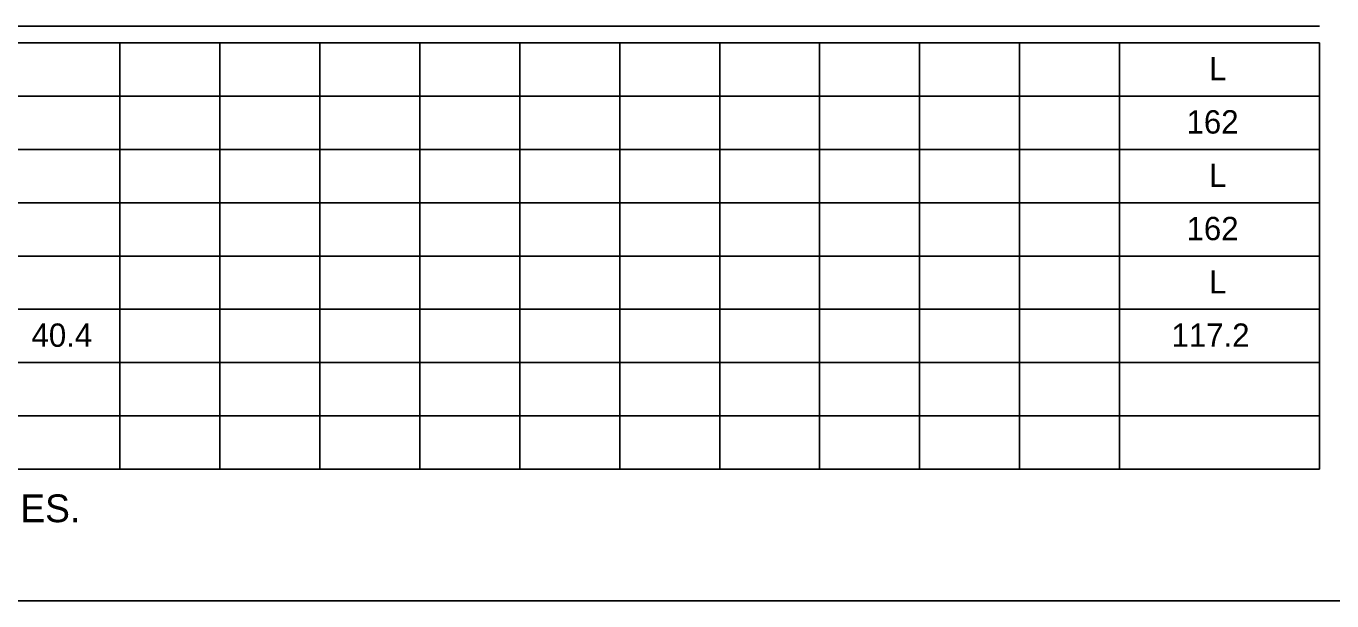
# Model space of a CAD drawing. Extents: x 10268312 to 10268472, y 2142583 to 2142688.
# Drawn here: x 10268355.16 to 10268394.36, y 2142640.28 to 2142657.53 of the extents above; entities that cross this region are included whole.
import ezdxf

# ---------------------------------------------------------------- set-up
doc = ezdxf.new("R2010")
doc.units = 0
for name, color, linetype in [('SheetBorder_dp', 7, 'Continuous'), ('SumBoxLines_dp', 7, 'Continuous'), ('SumBoxLinesMin_dp', 7, 'Continuous'), ('TextLabel', 7, 'Continuous'), ('TextNotes', 7, 'Continuous')]:
    doc.layers.add(name, color=color, linetype=linetype)

msp = doc.modelspace()

# ---------------------------------------------------------------- linework, layer by layer
at = {"layer": 'SheetBorder_dp'}
msp.add_line((10268317.73, 2142640.282), (10268471.73, 2142640.282), dxfattribs=at)
at = {"layer": 'SumBoxLines_dp'}
for p, q in [((10268341.73, 2142657.532), (10268393.98, 2142657.532)), ((10268318.48, 2142657.032), (10268393.98, 2142657.032)), ((10268357.98, 2142657.032), (10268357.98, 2142655.432)), ((10268360.98, 2142657.032), (10268360.98, 2142655.432)), ((10268363.98, 2142657.032), (10268363.98, 2142653.832)), ((10268366.98, 2142657.032), (10268366.98, 2142653.832)), ((10268369.98, 2142657.032), (10268369.98, 2142655.432)), ((10268372.98, 2142657.032), (10268372.98, 2142655.432)), ((10268375.98, 2142657.032), (10268375.98, 2142655.432)), ((10268378.98, 2142657.032), (10268378.98, 2142655.432)), ((10268381.98, 2142657.032), (10268381.98, 2142655.432)), ((10268384.98, 2142657.032), (10268384.98, 2142655.432)), ((10268387.98, 2142657.032), (10268387.98, 2142655.432)), ((10268393.98, 2142657.032), (10268393.98, 2142644.232)), ((10268357.98, 2142655.432), (10268357.98, 2142649.032)), ((10268360.98, 2142655.432), (10268360.98, 2142647.432)), ((10268363.98, 2142655.432), (10268363.98, 2142647.432)), ((10268366.98, 2142655.432), (10268366.98, 2142649.032)), ((10268369.98, 2142655.432), (10268369.98, 2142649.032)), ((10268372.98, 2142655.432), (10268372.98, 2142644.232)), ((10268375.98, 2142655.432), (10268375.98, 2142644.232)), ((10268378.98, 2142655.432), (10268378.98, 2142649.032)), ((10268381.98, 2142655.432), (10268381.98, 2142649.032)), ((10268384.98, 2142655.432), (10268384.98, 2142649.032)), ((10268387.98, 2142655.432), (10268387.98, 2142644.232)), ((10268318.48, 2142653.832), (10268393.98, 2142653.832)), ((10268318.48, 2142650.632), (10268393.98, 2142650.632)), ((10268357.98, 2142649.032), (10268357.98, 2142644.232)), ((10268366.98, 2142649.032), (10268366.98, 2142644.232)), ((10268369.98, 2142649.032), (10268369.98, 2142644.232)), ((10268378.98, 2142649.032), (10268378.98, 2142644.232)), ((10268381.98, 2142649.032), (10268381.98, 2142644.232)), ((10268384.98, 2142649.032), (10268384.98, 2142644.232)), ((10268318.48, 2142647.432), (10268393.98, 2142647.432)), ((10268360.98, 2142647.432), (10268360.98, 2142644.232)), ((10268363.98, 2142647.432), (10268363.98, 2142644.232)), ((10268318.48, 2142644.232), (10268393.98, 2142644.232))]:
    msp.add_line(p, q, dxfattribs=at)
at = {"layer": 'SumBoxLinesMin_dp'}
for p, q in [((10268318.48, 2142655.432), (10268393.98, 2142655.432)), ((10268318.48, 2142652.232), (10268393.98, 2142652.232)), ((10268318.48, 2142649.032), (10268393.98, 2142649.032)), ((10268318.48, 2142645.832), (10268393.98, 2142645.832))]:
    msp.add_line(p, q, dxfattribs=at)

# ---------------------------------------------------------------- texts
at = {"layer": 'TextLabel'}
for s, p in [('L', (10268390.668, 2142655.907)), ('162', (10268389.993, 2142654.307)), ('L', (10268390.668, 2142652.707)), ('162', (10268389.993, 2142651.107)), ('L', (10268390.668, 2142649.507)), ('40.4', (10268355.326, 2142647.907)), ('117.2', (10268389.541, 2142647.907))]:
    msp.add_text(s, height=0.7, dxfattribs=at).set_placement(p)
at = {"layer": 'TextNotes'}
msp.add_text('NOTE:  WIDTH - HORIZONTAL SPACING DIMENSIONS ARE IN INCHES.', height=0.83333, dxfattribs=at).set_placement((10268319.392, 2142642.643))

doc.saveas('drawing.dxf')
